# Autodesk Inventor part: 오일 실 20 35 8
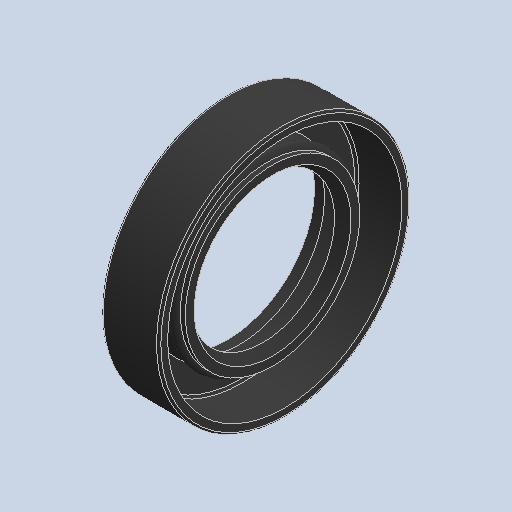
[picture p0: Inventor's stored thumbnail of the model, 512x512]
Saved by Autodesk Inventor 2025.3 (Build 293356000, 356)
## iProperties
Created: 2025-09
Part Number: 오일 실 20 35 8
Material: 고무
Description: 오일-실
Document SubType Name: Modeling
Designer: PC-15
Density: 0.93 g/cm^3
Appearance: 기본값
Author: jhkim
Sending System: Autodesk Inventor 2026
Preprocessor: ST-DEVELOPER v20.1
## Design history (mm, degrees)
feature "Solid1"
node "솔리드1"
